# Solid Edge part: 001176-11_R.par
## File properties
Last saved by: morva
Revision: 82
Accuracy: 0.990
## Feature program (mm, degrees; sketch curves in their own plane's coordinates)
body "unnamed Body 1"
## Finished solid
Body 1: solid body, 36 faces, 82 edges, 50 vertices.
  Faces by surface: cone 16, plane 10, cylinder 6, torus 4
  Edges by curve: circle 36, curve on surface 26, line 16, spline 4
Bounding box of the edges (mm; curved faces can reach further): 9.280 x 7.777 x 8.917, from (389.4222, 375.4607, 166.1772) to (398.7018, 383.2375, 175.0945).
Cylindrical faces by radius (mm): R2 x2, R2.5 x2, R3.75 x2
Conical faces (half-angle, radius in mm at the cone's reference point): 45 deg R2.5 x2, 45 deg R4.6225 x14
Toroidal faces (ring radius, tube radius in mm): R3.25 r0.5 x2, R3.95 r0.2 x2
Planar faces by outward normal: oblique 10
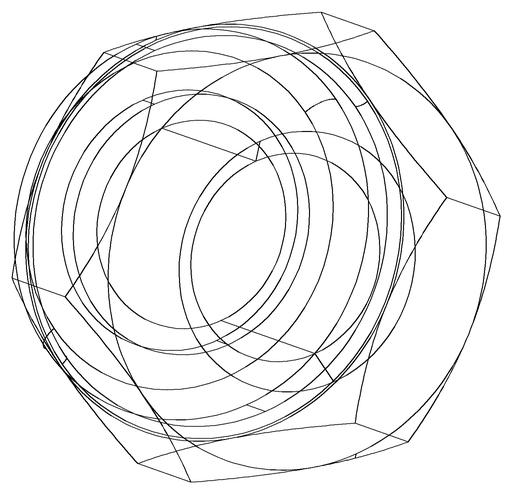
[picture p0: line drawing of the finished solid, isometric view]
